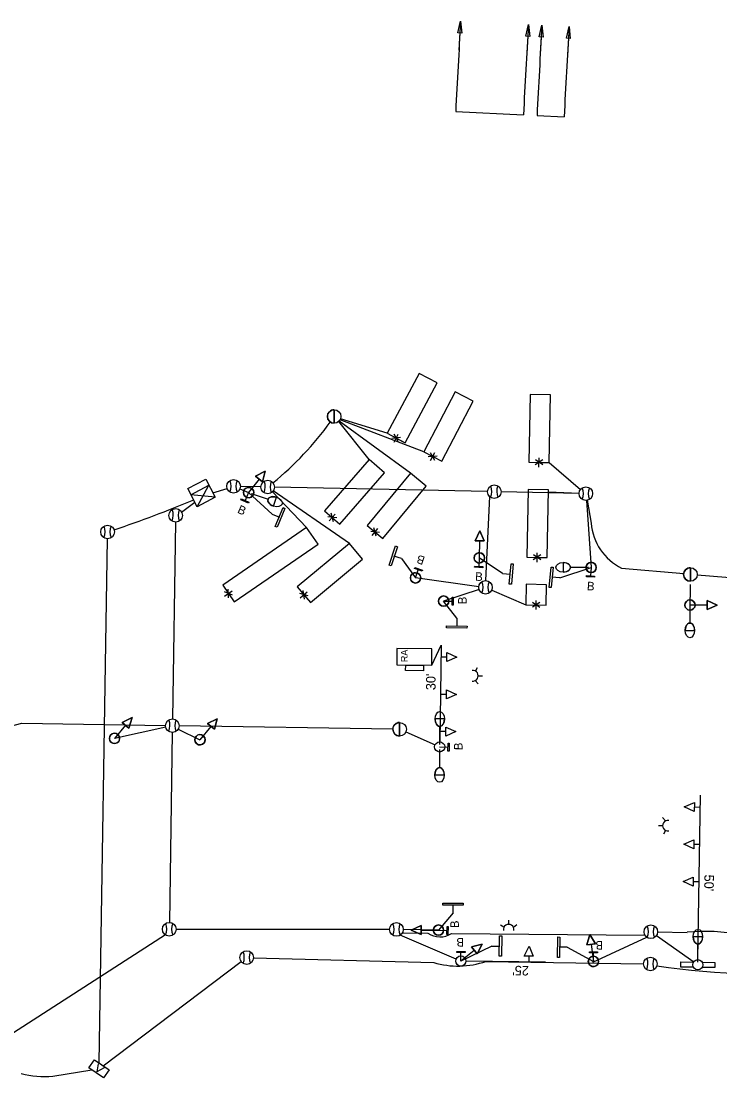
# Model space of a CAD drawing. Extents: x 596176 to 605330, y 332416 to 402398.
# Drawn here: x 602517.5 to 602723.5, y 366044.3 to 366355.8 of the extents above; entities that cross this region are included whole.
import ezdxf

# ---------------------------------------------------------------- set-up
doc = ezdxf.new("R2010")
doc.units = 0
for name, color, linetype in [('P_LTG', 7, 'Continuous'), ('P_SIG', 7, 'Continuous'), ('P_SIG_Bold', 7, 'Continuous'), ('P_SIG_Conduit', 7, 'Continuous'), ('P_SIG_IC', 7, 'Continuous'), ('P_SIG_Loops', 7, 'Continuous')]:
    doc.layers.add(name, color=color, linetype=linetype)

# ---------------------------------------------------------------- blocks, each defined once
blk = doc.blocks.new('_U322')
at = {"layer": 'P_LTG'}
for p, q in [((4.32, 25.12), (-4.14, 25.12)), ((0.05, 2.3), (0.05, 18.44))]:
    blk.add_line(p, q, dxfattribs=at)
blk.add_ellipse((0.09, 25.12), major_axis=(0, 6.65), ratio=0.636439, dxfattribs=at)
blk.add_ellipse((0.09, 25.12), major_axis=(0, 6.65), ratio=0.636439, start_param=1.570796, end_param=4.712389, dxfattribs=at)

msp = doc.modelspace()

# ---------------------------------------------------------------- linework, layer by layer
at = {"layer": 'P_SIG'}
for p, q in [((602609.8, 366241.29), (602609.78, 366237.29)), ((602566.64, 366218.02), (602571.96, 366220.79)), ((602566.64, 366218.02), (602571.96, 366220.79)), ((602567.56, 366216.24), (602572.88, 366219.01)), ((602567.56, 366216.24), (602572.88, 366219.01)), ((602569.41, 366212.7), (602572.88, 366219.01)), ((602569.41, 366212.7), (602572.88, 366219.01)), ((602571.96, 366220.79), (602574.73, 366215.46)), ((602571.96, 366220.79), (602574.73, 366215.46)), ((602587.64, 366220.85), (602584.56, 366216.84)), ((602569.41, 366212.7), (602566.64, 366218.02)), ((602569.41, 366212.7), (602566.64, 366218.02)), ((602574.73, 366215.46), (602567.56, 366216.24)), ((602574.73, 366215.46), (602567.56, 366216.24)), ((602584.56, 366216.84), (602583.55, 366214.55)), ((602591.47, 366210.49), (602584.56, 366216.84)), ((602574.73, 366215.46), (602569.41, 366212.7)), ((602574.73, 366215.46), (602569.41, 366212.7)), ((602591.47, 366210.49), (602593.69, 366209.57)), ((602652.66, 366202.66), (602652.57, 366197.61)), ((602629.66, 366197.38), (602627.39, 366198.16)), ((602629.66, 366197.38), (602633.78, 366191.72)), ((602652.57, 366197.61), (602652.4, 366195.11)), ((602659.4, 366193.02), (602652.57, 366197.61)), ((602633.78, 366191.72), (602634.58, 366194.08)), ((602676.31, 366191.69), (602685.53, 366194.79)), ((602685.53, 366194.79), (602685.35, 366192.3)), ((602714.81, 366194.71), (602714.79, 366190.71)), ((602659.4, 366193.02), (602661.79, 366192.82)), ((602676.31, 366191.69), (602673.92, 366191.91)), ((602642.06, 366184.86), (602644.56, 366184.82)), ((602645.93, 366179.8), (602642.06, 366184.86)), ((602719.73, 366183.7), (602714.67, 366183.71)), ((602645.93, 366179.8), (602645.9, 366177.4)), ((602638.59, 366165.97), (602641.35, 366171.87)), ((602642.96, 366168.37), (602641.19, 366168.37)), ((602651.41, 366164.25), (602652.01, 366165.33)), ((602652.24, 366162.88), (602653.47, 366162.88)), ((602651.39, 366161.46), (602652.27, 366160.47)), ((602642.9, 366157.37), (602641.12, 366157.37)), ((602548.29, 366148.26), (602545.03, 366144.39)), ((602573.45, 366147.89), (602570.23, 366143.99)), ((602629.08, 366149.07), (602629.06, 366145.07)), ((602642.67, 366146.4), (602640.89, 366146.4)), ((602640.85, 366141.86), (602643.35, 366141.81)), ((602715.96, 366124.18), (602717.73, 366124.15)), ((602707.46, 366120.06), (602706.58, 366121.05)), ((602706.62, 366118.65), (602705.39, 366118.65)), ((602707.44, 366117.27), (602706.84, 366116.2)), ((602715.78, 366113.18), (602717.55, 366113.16)), ((602715.61, 366102.18), (602717.38, 366102.16)), ((602644.88, 366092.97), (602644.88, 366095.37)), ((602644.88, 366092.97), (602640.52, 366087.87)), ((602659.84, 366088.75), (602658.77, 366089.35)), ((602661.23, 366089.55), (602661.24, 366090.78)), ((602662.63, 366088.69), (602663.63, 366089.56)), ((602635.47, 366087.89), (602640.52, 366087.87)), ((602640.52, 366087.87), (602643.02, 366087.79)), ((602656.25, 366083.15), (602647.11, 366078.76)), ((602651.08, 366081.9), (602647.11, 366078.76)), ((602656.25, 366083.15), (602658.65, 366083.11)), ((602678.49, 366082.84), (602676.09, 366082.87)), ((602678.49, 366082.84), (602686.22, 366078.65)), ((602685.53, 366083.66), (602686.22, 366078.65)), ((602647.11, 366078.76), (602647.16, 366081.26)), ((602667.16, 366080.2), (602667.12, 366078.43)), ((602686.22, 366078.65), (602686.22, 366081.15)), ((602540.22, 366048.47), (602539.86, 366046.09)), ((602541.94, 366047.3), (602539.86, 366046.09))]:
    msp.add_line(p, q, dxfattribs=at)
for points in [[(602609.78, 366237.29), (602609.8, 366241.29)], [(602589.44, 366223.2), (602588.69, 366220.05), (602586.59, 366221.65), (602589.44, 366223.2)], [(602588.69, 366220.05), (602589.44, 366223.2), (602586.59, 366221.65), (602588.69, 366220.05)], [(602652.7, 366205.62), (602653.97, 366202.65), (602651.34, 366202.68), (602652.7, 366205.62)], [(602653.97, 366202.65), (602652.7, 366205.62), (602651.34, 366202.68), (602653.97, 366202.65)], [(602714.79, 366190.71), (602714.81, 366194.71)], [(602722.69, 366183.7), (602719.73, 366182.38), (602719.73, 366185.02), (602722.69, 366183.7)], [(602719.73, 366182.38), (602722.69, 366183.7), (602719.73, 366185.02), (602719.73, 366182.38)], [(602550.19, 366150.52), (602549.3, 366147.41), (602547.28, 366149.11), (602550.19, 366150.52)], [(602549.3, 366147.41), (602550.19, 366150.52), (602547.28, 366149.11), (602549.3, 366147.41)], [(602575.33, 366150.18), (602574.47, 366147.06), (602572.43, 366148.73), (602575.33, 366150.18)], [(602574.47, 366147.06), (602575.33, 366150.18), (602572.43, 366148.73), (602574.47, 366147.06)], [(602629.06, 366145.07), (602629.08, 366149.07)], [(602632.51, 366087.89), (602635.47, 366089.2), (602635.47, 366086.57), (602632.51, 366087.89)], [(602635.47, 366089.2), (602632.51, 366087.89), (602635.47, 366086.57), (602635.47, 366089.2)], [(602685.12, 366086.59), (602686.84, 366083.84), (602684.23, 366083.48), (602685.12, 366086.59)], [(602686.84, 366083.84), (602685.12, 366086.59), (602684.23, 366083.48), (602686.84, 366083.84)], [(602653.4, 366083.74), (602651.9, 366080.87), (602650.26, 366082.93), (602653.4, 366083.74)], [(602653.4, 366083.74), (602651.9, 366080.87), (602650.26, 366082.93), (602653.4, 366083.74)], [(602651.9, 366080.87), (602653.4, 366083.74), (602650.26, 366082.93), (602651.9, 366080.87)]]:
    msp.add_lwpolyline(points, dxfattribs=at)
for points in [[(602582.45, 366215.04), (602584.65, 366214.07), (602584.52, 366213.77), (602582.32, 366214.74)], [(602592.43, 366206.89), (602594.73, 366212.43), (602595.29, 366212.2), (602592.98, 366206.66)], [(602628.46, 366200.91), (602626.54, 366195.23), (602625.97, 366195.42), (602627.89, 366201.11)], [(602635.72, 366193.7), (602633.45, 366194.47), (602633.55, 366194.78), (602635.83, 366194.01)], [(602651.2, 366195.19), (602653.6, 366195.03), (602653.57, 366194.71), (602651.18, 366194.87)], [(602661.41, 366189.89), (602661.92, 366195.86), (602662.52, 366195.81), (602662.01, 366189.83)], [(602674.31, 366194.84), (602673.78, 366188.86), (602673.18, 366188.92), (602673.72, 366194.89)], [(602684.16, 366192.39), (602686.55, 366192.22), (602686.53, 366191.89), (602684.13, 366192.06)], [(602644.55, 366183.62), (602644.58, 366186.02), (602644.9, 366186.02), (602644.87, 366183.62)], [(602642.94, 366177.58), (602648.94, 366177.49), (602648.93, 366176.89), (602642.93, 366176.98)], [(602638.62, 366170.79), (602628.28, 366170.86), (602628.24, 366166.04), (602638.59, 366165.97)], [(602645.92, 366168.37), (602642.96, 366167.06), (602642.96, 366169.69)], [(602630.86, 366164.39), (602630.87, 366165.99), (602636.14, 366165.95), (602636.13, 366164.35)], [(602645.85, 366157.37), (602642.9, 366156.06), (602642.9, 366158.69)], [(602645.62, 366146.4), (602642.67, 366145.09), (602642.67, 366147.72)], [(602643.33, 366140.61), (602643.37, 366143.01), (602643.7, 366143.01), (602643.66, 366140.61)], [(602713, 366124.23), (602715.98, 366125.5), (602715.94, 366122.87)], [(602712.82, 366113.23), (602715.8, 366114.5), (602715.76, 366111.87)], [(602712.65, 366102.23), (602715.63, 366103.5), (602715.59, 366100.87)], [(602647.84, 366095.24), (602641.84, 366095.23), (602641.84, 366095.83), (602647.84, 366095.83)], [(602642.98, 366086.59), (602643.06, 366088.98), (602643.39, 366088.97), (602643.3, 366086.58)], [(602658.47, 366080.15), (602658.56, 366086.15), (602659.16, 366086.14), (602659.07, 366080.14)], [(602676.27, 366085.83), (602676.18, 366079.83), (602675.58, 366079.84), (602675.67, 366085.84)], [(602667.22, 366083.16), (602668.47, 366080.17), (602665.84, 366080.23)], [(602648.36, 366081.24), (602645.96, 366081.29), (602645.97, 366081.61), (602648.37, 366081.57)], [(602687.42, 366081.15), (602685.02, 366081.15), (602685.02, 366081.47), (602687.42, 366081.47)], [(602539.15, 366049.65), (602543.46, 366046.71), (602541.82, 366044.31), (602537.51, 366047.24)]]:
    msp.add_lwpolyline(points, close=True, dxfattribs=at)
for centre, radius in [((602609.79, 366239.29), 2), ((602580.13, 366218.7), 2), ((602590.19, 366218.49), 2), ((602656.98, 366217.11), 2), ((602584.56, 366216.84), 1.52), ((602584.56, 366216.84), 1.52), ((602584.56, 366216.84), 1.52), ((602683.98, 366216.55), 2), ((602563.07, 366210.14), 2), ((602542.99, 366205.26), 2), ((602652.57, 366197.61), 1.52), ((602652.57, 366197.61), 1.52), ((602652.57, 366197.61), 1.52), ((602685.53, 366194.79), 1.52), ((602714.8, 366192.71), 2), ((602633.78, 366191.72), 1.52), ((602654.4, 366188.92), 2), ((602642.06, 366184.86), 1.52), ((602714.67, 366183.71), 1.52), ((602714.67, 366183.71), 1.52), ((602714.67, 366183.71), 1.52), ((602562.09, 366148.13), 2), ((602629.07, 366147.07), 2), ((602545.03, 366144.39), 1.52), ((602545.03, 366144.39), 1.52), ((602545.03, 366144.39), 1.52), ((602570.23, 366143.99), 1.52), ((602570.23, 366143.99), 1.52), ((602570.23, 366143.99), 1.52), ((602561.17, 366088.13), 2), ((602628.14, 366088.07), 2), ((602640.52, 366087.87), 1.52), ((602640.52, 366087.87), 1.52), ((602640.52, 366087.87), 1.52), ((602703.14, 366087.38), 2), ((602584.01, 366079.77), 2), ((602686.22, 366078.65), 1.52), ((602686.22, 366078.65), 1.52), ((602686.22, 366078.65), 1.52), ((602702.99, 366077.89), 2)]:
    msp.add_circle(centre, radius, dxfattribs=at)
for centre, radius, start, end in [((602609.79, 366239.29), 2, 89.7008, 180), ((602609.79, 366239.29), 2, 180, 269.7008), ((602575.06, 366218.74), 4.36, 336.6741, 22.5272), ((602585.2, 366218.75), 4.36, 157.5751, 203.4282), ((602585.12, 366218.52), 4.36, 336.6741, 22.5272), ((602595.26, 366218.53), 4.36, 157.5751, 203.4282), ((602651.91, 366217.14), 4.36, 336.6741, 22.5272), ((602662.05, 366217.15), 4.36, 157.5751, 203.4282), ((602584.56, 366216.84), 1.52, 52.6073, 232.6073), ((602584.56, 366216.84), 1.52, 232.6073, 52.6073), ((602678.91, 366216.58), 4.36, 336.6741, 22.5272), ((602689.05, 366216.59), 4.36, 157.5751, 203.4282), ((602558, 366210.18), 4.36, 336.6741, 22.5272), ((602568.14, 366210.19), 4.36, 157.5751, 203.4282), ((602537.92, 366205.29), 4.36, 336.6741, 22.5272), ((602548.06, 366205.3), 4.36, 157.5751, 203.4282), ((602652.57, 366197.61), 1.52, 89.1897, 269.1897), ((602652.57, 366197.61), 1.52, 269.1897, 89.1897), ((602685.53, 366194.79), 1.52, 0, 180), ((602685.53, 366194.79), 1.52, 180, 0), ((602714.8, 366192.71), 2, 89.7008, 180), ((602633.78, 366191.72), 1.52, 89.1897, 269.1897), ((602633.78, 366191.72), 1.52, 269.1897, 89.1897), ((602714.8, 366192.71), 2, 180, 269.7008), ((602649.33, 366188.96), 4.36, 336.6741, 22.5272), ((602659.47, 366188.97), 4.36, 157.5751, 203.4282), ((602642.06, 366184.86), 1.52, 0, 180), ((602642.06, 366184.86), 1.52, 180, 0), ((602714.67, 366183.71), 1.52, 0, 180), ((602714.67, 366183.71), 1.52, 180, 0), ((602650.66, 366162.86), 1.58, 262.3317, 97.8392), ((602557.02, 366148.16), 4.36, 336.6741, 22.5272), ((602567.16, 366148.17), 4.36, 157.5751, 203.4282), ((602629.07, 366147.07), 2, 89.7008, 180), ((602545.03, 366144.39), 1.52, 49.9699, 229.9699), ((602545.03, 366144.39), 1.52, 229.9699, 49.9699), ((602570.23, 366143.99), 1.52, 50.5662, 230.5662), ((602570.23, 366143.99), 1.52, 230.5662, 50.5662), ((602629.07, 366147.07), 2, 180, 269.7008), ((602708.19, 366118.66), 1.58, 82.3317, 277.8392), ((602556.1, 366088.17), 4.36, 336.6741, 22.5272), ((602566.24, 366088.18), 4.36, 157.5751, 203.4282), ((602623.07, 366088.11), 4.36, 336.6741, 22.5272), ((602633.21, 366088.12), 4.36, 157.5751, 203.4282), ((602640.52, 366087.87), 1.52, 0, 180), ((602661.22, 366087.98), 1.58, 351.7096, 187.2171), ((602698.07, 366087.42), 4.36, 336.6741, 22.5272), ((602708.21, 366087.42), 4.36, 157.5751, 203.4282), ((602640.52, 366087.87), 1.52, 180, 0), ((602578.94, 366079.81), 4.36, 336.6741, 22.5272), ((602589.08, 366079.82), 4.36, 157.5751, 203.4282), ((602686.22, 366078.65), 1.52, 97.9663, 277.9663), ((602686.22, 366078.65), 1.52, 277.9663, 97.9663), ((602697.92, 366077.92), 4.36, 336.6741, 22.5272), ((602708.06, 366077.93), 4.36, 157.5751, 203.4282)]:
    msp.add_arc(centre, radius, start, end, dxfattribs=at)
at = {"layer": 'P_SIG_Bold'}
for p, q in [((602641.35, 366171.87), (602640.9, 366143.37)), ((602717.01, 366079.16), (602717.78, 366127.65)), ((602672.11, 366078.37), (602648.61, 366078.74))]:
    msp.add_line(p, q, dxfattribs=at)
for points in [[(602715.68, 366076.93), (602711.98, 366076.99), (602712, 366078.49), (602715.7, 366078.43)], [(602718.3, 366078.39), (602722, 366078.33), (602721.98, 366076.83), (602718.28, 366076.89)]]:
    msp.add_lwpolyline(points, dxfattribs=at)
for centre in [(602640.88, 366141.87), (602647.11, 366078.76), (602716.99, 366077.66)]:
    msp.add_circle(centre, 1.5, dxfattribs=at)
at = {"layer": 'P_SIG_Conduit'}
for p, q in [((602574.04, 366216.79), (602578.23, 366218.1)), ((602581.98, 366217.93), (602584.56, 366216.84)), ((602588.19, 366218.53), (602582.13, 366218.66)), ((602654.98, 366217.14), (602592.19, 366218.45)), ((602681.98, 366216.58), (602658.98, 366217.06)), ((602564.81, 366211.13), (602568.7, 366214.05)), ((602655.59, 366215.67), (602654.44, 366190.9)), ((602563.04, 366208.14), (602562.12, 366150.13)), ((602652.4, 366189.09), (602633.78, 366191.72)), ((602652.49, 366188.32), (602642.06, 366184.86)), ((602560.13, 366147.7), (602545.03, 366144.39)), ((602627.07, 366147.09), (602564.09, 366148.09)), ((602562.06, 366146.13), (602561.2, 366090.13)), ((602563.8, 366147.1), (602570.23, 366143.99)), ((602630.92, 366146.29), (602639.51, 366142.48)), ((602563.17, 366088.13), (602626.14, 366088.1)), ((602560.08, 366086.45), (602509.25, 366053.76)), ((602686, 366078.42), (602701.95, 366085.78)), ((602704.78, 366086.23), (602715.76, 366078.52))]:
    msp.add_line(p, q, dxfattribs=at)
for points in [[(602684.12, 366214.55), (602685.53, 366194.79)], [(602684.33, 366214.58), (602685.53, 366207.83)], [(602694.5, 366194.53), (602712.82, 366192.97)], [(602716.8, 366192.63), (602745.78, 366190.29)], [(602714.77, 366189.71), (602714.65, 366182.21)], [(602488.97, 366141.28), (602517.76, 366148.83), (602560.09, 366148.16)], [(602640.52, 366087.87), (602630.14, 366088.04)], [(602645.73, 366079.35), (602629.22, 366086.38)], [(602629.86, 366087.04), (602637.43, 366086.97)], [(602644.35, 366086.91), (602701.4, 366086.39)], [(602705.14, 366087.35), (602713.86, 366087.21)]]:
    msp.add_lwpolyline(points, dxfattribs=at)
for centre, radius, start, end in [((602532.12, 366292.92), 94.4, 309.1709, 324.1581), ((602701.86, 366209.17), 16.38, 184.6971, 243.3135), ((602640.94, 366091.93), 6.07, 234.7371, 304.2288), ((602719.11, 366039.94), 47.57, 57.9898, 96.3464)]:
    msp.add_arc(centre, radius, start, end, dxfattribs=at)
at = {"layer": 'P_SIG_IC'}
for points in [[(602540.51, 366048.72), (602542.96, 366203.24)], [(602586.01, 366079.74), (602639.12, 366078.31)], [(602654.51, 366078.65), (602700.99, 366077.88)], [(602541.71, 366047.9), (602582.41, 366078.57)], [(602526.86, 366044.85), (602538.38, 366046.65)]]:
    msp.add_lwpolyline(points, dxfattribs=at)
for centre, radius, start, end in [((602419.22, 366576.86), 391.68, 288.7142, 292.3828), ((602646.29, 366102.42), 25.15, 253.4339, 289.078), ((602737.84, 366297.84), 222.95, 261.5069, 275.5534), ((602524.06, 366068.51), 23.82, 254.0384, 276.7577)]:
    msp.add_arc(centre, radius, start, end, dxfattribs=at)
at = {"layer": 'P_SIG_Loops'}
for p, q in [((602620.1, 366226.59), (602611.17, 366237.84)), ((602632.32, 366222.55), (602611.24, 366237.91)), ((602636.17, 366228.89), (602611.54, 366238.33)), ((602625.42, 366234.33), (602611.67, 366238.62)), ((602629.37, 366233.05), (602626.78, 366232.81)), ((602627.44, 366231.7), (602628.69, 366234.06)), ((602628.7, 366231.76), (602627.44, 366234.03)), ((602628.06, 366232.92), (602630.71, 366231.51)), ((602638.2, 366226.27), (602639.45, 366228.64)), ((602639.46, 366226.34), (602638.2, 366228.6)), ((602640.13, 366227.63), (602637.54, 366227.38)), ((602638.82, 366227.49), (602641.48, 366226.09)), ((602671.27, 366226.47), (602669.07, 366225.08)), ((602671.26, 366225.01), (602669.11, 366226.47)), ((602670.16, 366224.38), (602670.21, 366227.06)), ((602670.17, 366225.76), (602673.17, 366225.7)), ((602673.15, 366225.68), (602682.4, 366217.77)), ((602681.98, 366216.62), (602673, 366216.94)), ((602610.54, 366209.37), (602607.96, 366209.72)), ((602608.35, 366208.49), (602610.1, 366210.51)), ((602609.59, 366208.27), (602608.88, 366210.76)), ((602609.23, 366209.53), (602611.5, 366207.57)), ((602622.21, 366204.01), (602621.44, 366206.48)), ((602623.13, 366205.13), (602620.55, 366205.43)), ((602620.96, 366204.2), (602622.67, 366206.26)), ((602621.82, 366205.27), (602624.13, 366203.35)), ((602670.69, 366198.46), (602668.49, 366197.07)), ((602670.67, 366197), (602668.53, 366198.46)), ((602669.58, 366196.37), (602669.63, 366199.05)), ((602669.59, 366197.75), (602672.59, 366197.68)), ((602577.5, 366186.34), (602579.71, 366187.85)), ((602578.65, 366185.81), (602578.58, 366188.4)), ((602601, 366185.44), (602600.69, 366188.01)), ((602579.84, 366186.64), (602577.44, 366187.62)), ((602578.62, 366187.13), (602580.32, 366184.65)), ((602602.11, 366186.38), (602599.62, 366187.14)), ((602599.8, 366185.86), (602601.86, 366187.58)), ((602600.84, 366186.75), (602602.77, 366184.45)), ((602669.28, 366182.38), (602669.34, 366185.05)), ((602670.4, 366184.46), (602668.2, 366183.07)), ((602670.38, 366183.01), (602668.24, 366184.46)), ((602669.3, 366183.75), (602672.29, 366183.69))]:
    msp.add_line(p, q, dxfattribs=at)
for points in [[(602646.28, 366352.39), (602647.06, 366355.85), (602647.44, 366352.32)], [(602666.25, 366351.42), (602667.04, 366354.88), (602667.42, 366351.35)], [(602670.25, 366351.18), (602671.03, 366354.64), (602671.41, 366351.12)], [(602678.24, 366350.82), (602679.02, 366354.28), (602679.4, 366350.75)], [(602630.71, 366231.51), (602640.1, 366249.17), (602634.81, 366251.98), (602625.42, 366234.33)], [(602641.48, 366226.09), (602650.8, 366243.78), (602645.5, 366246.58), (602636.17, 366228.89)], [(602673.17, 366225.7), (602673.58, 366245.69), (602667.58, 366245.82), (602667.17, 366225.82)], [(602611.5, 366207.57), (602624.63, 366222.65), (602620.1, 366226.59), (602606.97, 366211.51)], [(602624.13, 366203.35), (602636.93, 366218.71), (602632.32, 366222.55), (602619.52, 366207.19)], [(602672.59, 366197.68), (602673, 366217.68), (602667, 366217.8), (602666.59, 366197.81)], [(602580.32, 366184.65), (602605.06, 366201.62), (602601.67, 366206.57), (602576.93, 366189.6)], [(602602.77, 366184.45), (602618.12, 366197.27), (602614.27, 366201.87), (602598.92, 366189.06)], [(602672.29, 366183.69), (602672.42, 366189.69), (602666.42, 366189.81), (602666.3, 366183.81)]]:
    msp.add_lwpolyline(points, close=True, dxfattribs=at)
for points in [[(602646.86, 366352.35), (602646.56, 366347.29)], [(602666.83, 366351.39), (602666.54, 366346.32)], [(602670.83, 366351.15), (602670.53, 366346.09)], [(602678.82, 366350.78), (602678.53, 366345.72)], [(602645.61, 366329.22), (602665.58, 366328.22)], [(602669.58, 366328.02), (602677.57, 366327.62)], [(602601.67, 366206.57), (602591.57, 366217.05)], [(602614.27, 366201.87), (602591.83, 366217.35)], [(602656.24, 366188.13), (602666.3, 366183.81)]]:
    msp.add_lwpolyline(points, dxfattribs=at)
for centre, radius in [((605648.83, 366178.55), 3007), ((605672.8, 366177.34), 3011), ((605672.8, 366177.34), 3007), ((605684.78, 366176.74), 3011)]:
    msp.add_arc(centre, radius, 176.61975, 177.12785, dxfattribs=at)

# ---------------------------------------------------------------- block references
at = {"layer": 'P_LTG', "xscale": 0.32808333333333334}
for p, yscale, rotation in [((602584.56, 366216.84), 0.3280833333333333, -108.71801817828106), ((602685.53, 366194.79), 0.32808333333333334, 90), ((602714.69, 366184.46), 0.32808333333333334, 180), ((602640.88, 366141.87), 0.32808333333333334, 180)]:
    msp.add_blockref('_U322', p, dxfattribs=dict(at, yscale=yscale, rotation=rotation))
at = {"layer": 'P_LTG', "xscale": 0.32808333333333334, "yscale": 0.32808333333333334}
for p in [(602640.88, 366141.87), (602716.99, 366077.66)]:
    msp.add_blockref('_U322', p, dxfattribs=at)

# ---------------------------------------------------------------- texts
at = {"layer": 'P_SIG'}
for s, height, rotation, p in [('B', 2.52, 336.2727, (602581.06, 366210.98)), ('B', 2.52, 161.282, (602636.75, 366197.86)), ('B', 2.52, 356.1527, (602651.27, 366190.91)), ('B', 2.52, 356.0144, (602684.22, 366188.1)), ('B', 2.52, 89.2055, (602648.82, 366183.92)), ('RA', 2, 89.6023, (602631.44, 366166.84)), ('B', 2.52, 89.0401, (602647.61, 366140.9)), ("50'", 2.8, 269.0919, (602718.93, 366104.25)), ('B', 2.52, 90, (602646.55, 366088.46)), ('B', 2.52, 178.9029, (602648.08, 366085.52)), ('B', 2.52, 180, (602689.06, 366084.65))]:
    msp.add_text(s, height=height, rotation=rotation, dxfattribs=at).set_placement(p)
at = {"layer": 'P_SIG_Bold'}
for s, rotation, p in [("30'", 90, (602639.67, 366158.6)), ("25'", 179.0919, (602667.2, 366077.28))]:
    msp.add_text(s, height=2.8, rotation=rotation, dxfattribs=at).set_placement(p)

doc.saveas('drawing.dxf')
